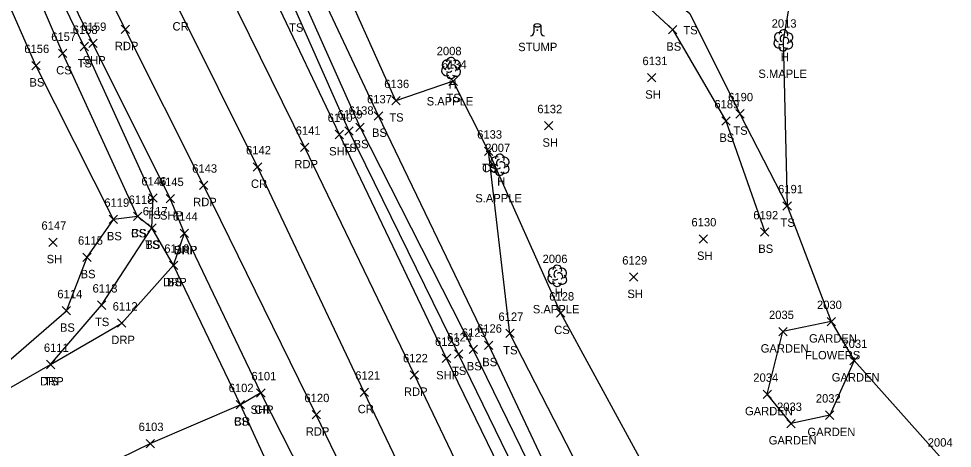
# Model space of a CAD drawing. Extents: x 1439173 to 1457902, y 641926 to 659889.
# Drawn here: x 1448995.2 to 1449218.3, y 643333 to 643435.5 of the extents above; entities that cross this region are included whole.
import ezdxf

# ---------------------------------------------------------------- set-up
doc = ezdxf.new("R2010")
doc.units = 0
for name, color, linetype in [('L_A', 7, 'Continuous'), ('L_C', 7, 'Continuous'), ('L_I', 7, 'Continuous'), ('L_TIC', 7, 'Continuous'), ('LAPB', 7, 'Continuous'), ('LELB', 7, 'Continuous'), ('LSOGP', 7, 'Continuous'), ('LTD', 7, 'Continuous'), ('LTS', 7, 'Continuous'), ('P_A', 7, 'Continuous'), ('P_I', 7, 'Continuous'), ('P_TIC', 7, 'Continuous'), ('PET', 7, 'Continuous'), ('PRC', 7, 'Continuous'), ('PSP', 7, 'Continuous'), ('R_A', 7, 'Continuous'), ('R_I', 7, 'Continuous'), ('R_TIC', 7, 'Continuous'), ('RDP', 7, 'Continuous')]:
    doc.layers.add(name, color=color, linetype=linetype)

msp = doc.modelspace()

# ---------------------------------------------------------------- linework, layer by layer
at = {"layer": 'L_TIC'}
for points in [[(1449150.53, 643431.82), (1449152.53, 643433.82)], [(1449152.53, 643431.82), (1449150.53, 643433.82)], [(1449004.76, 643426.17), (1449006.76, 643428.17)], [(1449006.76, 643426.17), (1449004.76, 643428.17)], [(1449009.91, 643427.83), (1449011.91, 643429.83)], [(1449011.91, 643427.83), (1449009.91, 643429.83)], [(1448998.38, 643423.27), (1449000.38, 643425.27)], [(1449000.38, 643423.27), (1448998.38, 643425.27)], [(1449098.06, 643419.55), (1449100.06, 643421.55)], [(1449100.06, 643419.55), (1449098.06, 643421.55)], [(1449145.46, 643420.38), (1449147.46, 643422.38)], [(1449147.46, 643420.38), (1449145.46, 643422.38)], [(1449084.39, 643414.9), (1449086.39, 643416.9)], [(1449086.39, 643414.9), (1449084.39, 643416.9)], [(1449080.22, 643411.26), (1449082.22, 643413.26)], [(1449082.22, 643411.26), (1449080.22, 643413.26)], [(1449166.59, 643411.76), (1449168.59, 643413.76)], [(1449168.59, 643411.76), (1449166.59, 643413.76)], [(1449075.83, 643408.55), (1449077.83, 643410.55)], [(1449077.83, 643408.55), (1449075.83, 643410.55)], [(1449120.91, 643408.91), (1449122.91, 643410.91)], [(1449122.91, 643408.91), (1449120.91, 643410.91)], [(1449163.22, 643410.07), (1449165.22, 643412.07)], [(1449165.22, 643410.07), (1449163.22, 643412.07)], [(1449073.19, 643407.65), (1449075.19, 643409.65)], [(1449075.19, 643407.65), (1449073.19, 643409.65)], [(1449106.53, 643402.84), (1449108.53, 643404.84)], [(1449108.53, 643402.84), (1449106.53, 643404.84)], [(1449106.53, 643402.84), (1449108.53, 643404.84)], [(1449108.53, 643402.84), (1449106.53, 643404.84)], [(1449026.37, 643391.66), (1449028.37, 643393.66)], [(1449028.37, 643391.66), (1449026.37, 643393.66)], [(1449177.86, 643389.8), (1449179.86, 643391.8)], [(1449179.86, 643389.8), (1449177.86, 643391.8)], [(1449016.88, 643386.58), (1449018.88, 643388.58)], [(1449018.88, 643386.58), (1449016.88, 643388.58)], [(1449016.88, 643386.58), (1449018.88, 643388.58)], [(1449018.88, 643386.58), (1449016.88, 643388.58)], [(1449022.67, 643387.28), (1449024.67, 643389.28)], [(1449024.67, 643387.28), (1449022.67, 643389.28)], [(1449022.67, 643387.28), (1449024.67, 643389.28)], [(1449024.67, 643387.28), (1449022.67, 643389.28)], [(1449026.07, 643384.54), (1449028.07, 643386.54)], [(1449028.07, 643384.54), (1449026.07, 643386.54)], [(1449026.07, 643384.54), (1449028.07, 643386.54)], [(1449028.07, 643384.54), (1449026.07, 643386.54)], [(1449172.51, 643383.58), (1449174.51, 643385.58)], [(1449174.51, 643383.58), (1449172.51, 643385.58)], [(1449157.82, 643381.9), (1449159.82, 643383.9)], [(1449159.82, 643381.9), (1449157.82, 643383.9)], [(1449002.43, 643381.11), (1449004.43, 643383.11)], [(1449004.43, 643381.11), (1449002.43, 643383.11)], [(1449010.59, 643377.53), (1449012.59, 643379.53)], [(1449012.59, 643377.53), (1449010.59, 643379.53)], [(1449031.25, 643375.62), (1449033.25, 643377.62)], [(1449033.25, 643375.62), (1449031.25, 643377.62)], [(1449141.19, 643372.8), (1449143.19, 643374.8)], [(1449143.19, 643372.8), (1449141.19, 643374.8)], [(1449014.06, 643366.11), (1449016.06, 643368.11)], [(1449016.06, 643366.11), (1449014.06, 643368.11)], [(1449005.66, 643364.76), (1449007.66, 643366.76)], [(1449007.66, 643364.76), (1449005.66, 643366.76)], [(1449123.75, 643364.21), (1449125.75, 643366.21)], [(1449125.75, 643364.21), (1449123.75, 643366.21)], [(1449188.41, 643362.18), (1449190.41, 643364.18)], [(1449190.41, 643362.18), (1449188.41, 643364.18)], [(1449188.41, 643362.18), (1449190.41, 643364.18)], [(1449190.41, 643362.18), (1449188.41, 643364.18)], [(1449111.62, 643359.36), (1449113.62, 643361.36)], [(1449113.62, 643359.36), (1449111.62, 643361.36)], [(1449176.86, 643359.79), (1449178.86, 643361.79)], [(1449178.86, 643359.79), (1449176.86, 643361.79)], [(1449176.86, 643359.79), (1449178.86, 643361.79)], [(1449178.86, 643359.79), (1449176.86, 643361.79)], [(1449099.36, 643354.44), (1449101.36, 643356.44)], [(1449101.36, 643354.44), (1449099.36, 643356.44)], [(1449102.87, 643355.55), (1449104.87, 643357.55)], [(1449104.87, 643355.55), (1449102.87, 643357.55)], [(1449106.56, 643356.54), (1449108.56, 643358.54)], [(1449108.56, 643356.54), (1449106.56, 643358.54)], [(1449193.84, 643352.89), (1449195.84, 643354.89)], [(1449195.84, 643352.89), (1449193.84, 643354.89)], [(1449001.87, 643351.95), (1449003.87, 643353.95)], [(1449003.87, 643351.95), (1449001.87, 643353.95)], [(1449173.11, 643344.83), (1449175.11, 643346.83)], [(1449175.11, 643344.83), (1449173.11, 643346.83)], [(1449047.24, 643342.36), (1449049.24, 643344.36)], [(1449049.24, 643342.36), (1449047.24, 643344.36)], [(1449188.04, 643339.86), (1449190.04, 643341.86)], [(1449190.04, 643339.86), (1449188.04, 643341.86)], [(1449178.78, 643337.86), (1449180.78, 643339.86)], [(1449180.78, 643337.86), (1449178.78, 643339.86)]]:
    msp.add_lwpolyline(points, dxfattribs=at)
at = {"layer": 'LAPB'}
for points in [[(1449189.41, 643363.18), (1449194.84, 643353.89), (1449189.04, 643340.86), (1449179.78, 643338.86), (1449174.11, 643345.83), (1449177.86, 643360.79)], [(1449189.41, 643363.18), (1449177.86, 643360.79)]]:
    msp.add_lwpolyline(points, dxfattribs=at)
at = {"layer": 'LELB'}
for points in [[(1449002.87, 643352.95), (1449015.06, 643367.11), (1449027.07, 643385.54), (1449027.37, 643392.66), (1449010.91, 643428.83), (1448990.64, 643470.1), (1448981.71, 643489.28), (1448973.52, 643506.02), (1448960.88, 643532.41), (1448957.69, 643539.66), (1448946.95, 643564.12), (1448940.79, 643577.93), (1448919.27, 643624.16)], [(1449057.52, 643323.2), (1449048.24, 643343.36), (1449032.25, 643376.62), (1449027.07, 643385.54), (1449023.67, 643388.28), (1449017.88, 643387.58), (1448999.38, 643424.27), (1448981.06, 643465.9), (1448978.91, 643484.15), (1448958.17, 643480.5)], [(1449023.67, 643388.28), (1449005.76, 643427.17), (1448987.76, 643468.8), (1448978.91, 643484.15)], [(1449171.86, 643204.27), (1449152.52, 643247.03), (1449132.22, 643288.76), (1449122.38, 643310.12), (1449100.36, 643355.44), (1449074.19, 643408.65), (1449061.44, 643437.34), (1449058.46, 643446.18), (1449059.5, 643448.74), (1449063.87, 643451.99), (1449068.54, 643452.64), (1449093.96, 643455.36), (1449106.86, 643455.84), (1449118.71, 643456.31), (1449141.25, 643448.31), (1449155.64, 643436.72), (1449167.59, 643412.76), (1449178.86, 643390.8)], [(1449185.52, 643209.06), (1449166.12, 643252.93), (1449146.62, 643293.4), (1449135.25, 643316.37), (1449112.62, 643360.36), (1449107.53, 643403.84), (1449099.06, 643420.55), (1449085.39, 643415.9), (1449070.11, 643449.83), (1449068.54, 643452.64)], [(1449118.97, 643452.28), (1449140.04, 643443.48), (1449151.53, 643432.82), (1449164.22, 643411.07), (1449173.51, 643384.58)], [(1449127.84, 643314.62), (1449107.56, 643357.54), (1449081.22, 643412.26), (1449064.59, 643447.64), (1449062.09, 643448.65), (1449060.63, 643447.6), (1449062.19, 643442.41)], [(1449125.22, 643312.87), (1449103.87, 643356.55), (1449076.83, 643409.55), (1449062.19, 643442.41)], [(1449197.24, 643213.11), (1449176.08, 643257.09), (1449156.69, 643299.92), (1449147.93, 643322.72), (1449124.75, 643365.21), (1449107.53, 643403.84)], [(1448958.67, 643334.28), (1448987.94, 643349.59), (1449006.66, 643365.76), (1449011.59, 643378.53), (1449017.88, 643387.58)]]:
    msp.add_lwpolyline(points, dxfattribs=at)
at = {"layer": 'LSOGP'}
msp.add_lwpolyline([(1449183.75, 643464.06), (1449177.92, 643430.32), (1449178.86, 643390.8), (1449189.41, 643363.18), (1449194.83, 643353.9), (1449215.87, 643330.35)], dxfattribs=at)
at = {"layer": 'LTD'}
for p, q in [((1449177.92, 643430.32), (1449177.92, 643430.32)), ((1449177.92, 643430.32), (1449177.92, 643430.32)), ((1449098.54, 643423.75), (1449098.54, 643423.75)), ((1449098.54, 643423.75), (1449098.54, 643423.75)), ((1449110.15, 643400.64), (1449110.15, 643400.64)), ((1449110.15, 643400.64), (1449110.15, 643400.64)), ((1449123.9, 643374.15), (1449123.9, 643374.15)), ((1449123.9, 643374.15), (1449123.9, 643374.15))]:
    msp.add_line(p, q, dxfattribs=at)
for centre in [(1449177.97, 643431.76), (1449098.58, 643425.19), (1449110.2, 643402.07), (1449123.94, 643375.58)]:
    msp.add_arc(centre, 1.05, 335.5272, 180.9563, dxfattribs=at)
for centre, major_axis, ratio, start_param, end_param in [((1449177.13, 643430.99), (1.21, -0.51), 0.895232, 1.570796, 4.712389), ((1449178.96, 643430.91), (-1.14, -0.48), 0.949671, 1.570796, 4.712389), ((1449176.84, 643429.61), (0.58, -1.04), 0.959034, 3.141593, 6.283185), ((1449177.71, 643430.78), (-0.208, -0.792), 0.645439, 3.141593, 6.283185), ((1449178.42, 643430.16), (-0.5, 0.667), 0.989748, 3.141593, 6.283185), ((1449178.92, 643429.49), (-1.09, 0.79), 0.841452, 1.570796, 4.712389), ((1449177.92, 643428.82), (0.26, 1.06), 0.942809, 1.570796, 4.712389), ((1449177.46, 643429.57), (-0.625, -0.083), 0.423636, 0, 3.141593), ((1449097.74, 643424.42), (1.21, -0.51), 0.895232, 1.570796, 4.712389), ((1449099.58, 643424.34), (-1.14, -0.48), 0.949671, 1.570796, 4.712389), ((1449097.45, 643423.04), (0.58, -1.04), 0.959034, 3.141593, 6.283185), ((1449098.33, 643424.21), (-0.208, -0.792), 0.645439, 3.141593, 6.283185), ((1449099.04, 643423.59), (-0.5, 0.667), 0.989748, 3.141593, 6.283185), ((1449099.54, 643422.92), (-1.09, 0.79), 0.841452, 1.570796, 4.712389), ((1449098.54, 643422.25), (0.26, 1.06), 0.942809, 1.570796, 4.712389), ((1449098.08, 643423), (-0.625, -0.083), 0.423636, 0, 3.141593), ((1449109.36, 643401.31), (1.21, -0.51), 0.895232, 1.570796, 4.712389), ((1449109.94, 643401.1), (-0.208, -0.792), 0.645439, 3.141593, 6.283185), ((1449110.65, 643400.47), (-0.5, 0.667), 0.989748, 3.141593, 6.283185), ((1449111.19, 643401.22), (-1.14, -0.48), 0.949671, 1.570796, 4.712389), ((1449109.07, 643399.93), (0.58, -1.04), 0.959034, 3.141593, 6.283185), ((1449110.15, 643399.14), (0.26, 1.06), 0.942809, 1.570796, 4.712389), ((1449109.69, 643399.89), (-0.625, -0.083), 0.423636, 0, 3.141593), ((1449111.15, 643399.81), (-1.09, 0.79), 0.841452, 1.570796, 4.712389), ((1449122.81, 643373.44), (0.58, -1.04), 0.959034, 3.141593, 6.283185), ((1449123.11, 643374.82), (1.21, -0.51), 0.895232, 1.570796, 4.712389), ((1449123.69, 643374.61), (-0.208, -0.792), 0.645439, 3.141593, 6.283185), ((1449124.4, 643373.98), (-0.5, 0.667), 0.989748, 3.141593, 6.283185), ((1449124.94, 643374.73), (-1.14, -0.48), 0.949671, 1.570796, 4.712389), ((1449123.9, 643372.65), (0.26, 1.06), 0.942809, 1.570796, 4.712389), ((1449123.44, 643373.4), (-0.625, -0.083), 0.423636, 0, 3.141593), ((1449124.9, 643373.32), (-1.09, 0.79), 0.841452, 1.570796, 4.712389)]:
    msp.add_ellipse(centre, major_axis=major_axis, ratio=ratio, start_param=start_param, end_param=end_param, dxfattribs=at)
at = {"layer": 'LTS'}
for p, q in [((1449118.34, 643433.86), (1449118.34, 643432.19)), ((1449119.17, 643432.71), (1449119.17, 643432.71)), ((1449119.17, 643432.71), (1449119.17, 643432.71)), ((1449119.17, 643432.69), (1449119.17, 643432.69)), ((1449120, 643433.69), (1449120, 643433.86)), ((1449120, 643433.86), (1449120, 643432.19))]:
    msp.add_line(p, q, dxfattribs=at)
msp.add_circle((1449119.17, 643432.71), 0.0833, dxfattribs=at)
for centre, start, end in [((1449117.5, 643432.19), 270, 360), ((1449120.84, 643432.19), 180, 270)]:
    msp.add_arc(centre, 0.833, start, end, dxfattribs=at)
msp.add_ellipse((1449119.17, 643433.86), major_axis=(-0.833, 0), ratio=0.5, dxfattribs=at)
at = {"layer": 'P_TIC'}
for points in [[(1449019.72, 643431.95), (1449021.72, 643433.95)], [(1449021.72, 643431.95), (1449019.72, 643433.95)], [(1449011.98, 643428.55), (1449013.98, 643430.55)], [(1449013.98, 643428.55), (1449011.98, 643430.55)], [(1449070.88, 643406.83), (1449072.88, 643408.83)], [(1449072.88, 643406.83), (1449070.88, 643408.83)], [(1449062.61, 643403.76), (1449064.61, 643405.76)], [(1449064.61, 643403.76), (1449062.61, 643405.76)], [(1449051.31, 643399.08), (1449053.31, 643401.08)], [(1449053.31, 643399.08), (1449051.31, 643401.08)], [(1449038.44, 643394.72), (1449040.44, 643396.72)], [(1449040.44, 643394.72), (1449038.44, 643396.72)], [(1449030.47, 643391.52), (1449032.47, 643393.52)], [(1449032.47, 643391.52), (1449030.47, 643393.52)], [(1449033.83, 643383.26), (1449035.83, 643385.26)], [(1449035.83, 643383.26), (1449033.83, 643385.26)], [(1449096.46, 643353.4), (1449098.46, 643355.4)], [(1449098.46, 643353.4), (1449096.46, 643355.4)], [(1449088.8, 643349.47), (1449090.8, 643351.47)], [(1449090.8, 643349.47), (1449088.8, 643351.47)], [(1449052.1, 643345.18), (1449054.1, 643347.18)], [(1449054.1, 643345.18), (1449052.1, 643347.18)], [(1449052.1, 643345.18), (1449054.1, 643347.18)], [(1449054.1, 643345.18), (1449052.1, 643347.18)], [(1449076.82, 643345.33), (1449078.82, 643347.33)], [(1449078.82, 643345.33), (1449076.82, 643347.33)], [(1449047.24, 643342.36), (1449049.24, 643344.36)], [(1449049.24, 643342.36), (1449047.24, 643344.36)], [(1449065.34, 643339.97), (1449067.34, 643341.97)], [(1449067.34, 643339.97), (1449065.34, 643341.97)], [(1449025.71, 643333.07), (1449027.71, 643335.07)], [(1449027.71, 643333.07), (1449025.71, 643335.07)]]:
    msp.add_lwpolyline(points, dxfattribs=at)
at = {"layer": 'PET'}
for points in [[(1449162.58, 643198.27), (1449141.48, 643242.39), (1449121.69, 643284.02), (1449089.8, 643350.47), (1449063.61, 643404.76), (1449045.09, 643442.41), (1449024.86, 643484.45), (1449010.1, 643514.11), (1448990.81, 643553.04), (1448970.84, 643592.72), (1448947.22, 643637.96), (1448929.6, 643671.83), (1448913.03, 643703.21), (1448880.27, 643765.4), (1448860.14, 643803.65), (1448849.29, 643824.32), (1448831.93, 643857), (1448813.55, 643891.18), (1448792.86, 643930.51), (1448774.91, 643964.18), (1448756.71, 643999.72), (1448741.68, 644029.9), (1448721.66, 644072.11)], [(1449139.97, 643188.13), (1449117.6, 643232.77), (1449099.11, 643273.2), (1449066.34, 643340.97), (1449039.44, 643395.72), (1449020.72, 643432.95), (1449000.27, 643474.21), (1448984.45, 643505.7), (1448966.63, 643542.12), (1448946.78, 643580.8), (1448923.53, 643626.67), (1448906.33, 643660.76), (1448890.57, 643691.55), (1448882.77, 643706.14), (1448861.66, 643747.38), (1448842.89, 643782.5), (1448829.18, 643808.28), (1448815.05, 643835.06), (1448764.92, 643929.88), (1448739.21, 643978.47), (1448719.14, 644017.8), (1448697.57, 644061.64)]]:
    msp.add_lwpolyline(points, dxfattribs=at)
at = {"layer": 'PRC'}
for points in [[(1449151.13, 643193.26), (1449129.92, 643237.18), (1449110.21, 643278.66), (1449077.82, 643346.33), (1449052.31, 643400.08), (1449033.57, 643437.64), (1449013.31, 643480.22), (1448998.17, 643509.98), (1448979.42, 643547.94), (1448960, 643587.03), (1448936.54, 643632.54), (1448918.64, 643666.68), (1448902.12, 643697.96), (1448893.71, 643713.68), (1448873.04, 643753.33), (1448854.51, 643788.55), (1448840.55, 643814.74), (1448825.9, 643842.48), (1448798.39, 643894.2), (1448777.05, 643935.06), (1448750.78, 643985.2), (1448731.14, 644023.28), (1448710.46, 644067.89)], [(1449053.1, 643346.18), (1449048.24, 643343.36), (1449026.71, 643334.07), (1449004.57, 643323.28), (1448976.4, 643308.88)]]:
    msp.add_lwpolyline(points, dxfattribs=at)
at = {"layer": 'PSP'}
for points in [[(1449169.82, 643203.27), (1449149.93, 643245.98), (1449130.54, 643285.72), (1449118.39, 643311.34), (1449097.46, 643354.4), (1449071.88, 643407.83), (1449056.01, 643441.14), (1449042.63, 643467.59), (1449032.61, 643488.35), (1449017.97, 643518.51), (1449011.01, 643533.15), (1448991.34, 643572.89), (1448977.12, 643597.86), (1448952.22, 643640.32)], [(1449131.44, 643184.41), (1449109.56, 643229.09), (1449090.46, 643269.75), (1449065.76, 643321.33), (1449053.1, 643346.18), (1449034.83, 643384.26), (1449031.47, 643392.52), (1449012.98, 643429.55), (1448992.54, 643471.26), (1448985.02, 643487.75), (1448974.42, 643508.35), (1448960.29, 643539.72), (1448943.46, 643579.59), (1448921.84, 643625.91)]]:
    msp.add_lwpolyline(points, dxfattribs=at)
at = {"layer": 'R_TIC'}
for points in [[(1449033.83, 643383.26), (1449035.83, 643385.26)], [(1449035.83, 643383.26), (1449033.83, 643385.26)], [(1449031.25, 643375.62), (1449033.25, 643377.62)], [(1449033.25, 643375.62), (1449031.25, 643377.62)], [(1449018.88, 643361.82), (1449020.88, 643363.82)], [(1449020.88, 643361.82), (1449018.88, 643363.82)], [(1449001.87, 643351.95), (1449003.87, 643353.95)], [(1449003.87, 643351.95), (1449001.87, 643353.95)]]:
    msp.add_lwpolyline(points, dxfattribs=at)
at = {"layer": 'RDP'}
msp.add_lwpolyline([(1448963.13, 643329.54), (1448990.18, 643345.74), (1449002.87, 643352.95), (1449019.88, 643362.82), (1449032.25, 643376.62), (1449034.83, 643384.26)], dxfattribs=at)

# ---------------------------------------------------------------- texts
at = {"layer": 'L_A'}
for s, p in [('TS', (1449059.85, 643432.34)), ('TS', (1449154.05, 643431.72)), ('STUMP', (1449114.59, 643427.72)), ('BS', (1449149.97, 643427.82)), ('TS', (1449009.32, 643423.83)), ('H', (1449177.35, 643425.32)), ('CS', (1449004.2, 643422.17)), ('BS', (1448997.82, 643419.27)), ('H', (1449097.97, 643418.75)), ('TS', (1449097.47, 643415.55)), ('SH', (1449144.95, 643416.38)), ('TS', (1449083.8, 643410.9)), ('BS', (1449079.66, 643407.26)), ('BS', (1449162.66, 643406.07)), ('TS', (1449166, 643407.76)), ('TS', (1449072.6, 643403.65)), ('BS', (1449075.27, 643404.55)), ('SH', (1449120.4, 643404.91)), ('TS', (1449105.94, 643398.84)), ('CS', (1449105.97, 643398.84)), ('H', (1449109.58, 643395.64)), ('TS', (1449025.78, 643387.66)), ('TS', (1449177.27, 643385.8)), ('BS', (1449016.32, 643382.58)), ('BS', (1449016.32, 643382.58)), ('CS', (1449022.11, 643383.28)), ('BS', (1449022.11, 643383.28)), ('TS', (1449025.48, 643380.54)), ('BS', (1449025.51, 643380.54)), ('BS', (1449171.95, 643379.58)), ('SH', (1449001.92, 643377.11)), ('SH', (1449157.31, 643377.9)), ('BS', (1449010.04, 643373.53)), ('BS', (1449030.69, 643371.62)), ('H', (1449123.33, 643369.15)), ('SH', (1449140.68, 643368.8)), ('TS', (1449013.47, 643362.11)), ('BS', (1449005.1, 643360.76)), ('CS', (1449123.19, 643360.21)), ('GARDEN', (1449184.08, 643358.18)), ('GARDEN', (1449184.08, 643358.18)), ('TS', (1449111.02, 643355.36)), ('GARDEN', (1449172.53, 643355.79)), ('GARDEN', (1449172.53, 643355.79)), ('BS', (1449106, 643352.54)), ('TS', (1449098.77, 643350.44)), ('BS', (1449102.31, 643351.55)), ('TS', (1449001.28, 643347.95)), ('GARDEN', (1449189.51, 643348.89)), ('GARDEN', (1449168.78, 643340.83)), ('BS', (1449046.68, 643338.36)), ('GARDEN', (1449183.71, 643335.86)), ('GARDEN', (1449174.45, 643333.86))]:
    msp.add_text(s, height=2, dxfattribs=at).set_placement(p)
at = {"layer": 'L_C'}
for s, p in [('S.MAPLE', (1449171.98, 643421.32)), ('S.APPLE', (1449092.72, 643414.75)), ('S.APPLE', (1449104.34, 643391.64)), ('S.APPLE', (1449118.09, 643365.15)), ('FLOWERS', (1449183.11, 643354.18)), ('FLOWERS', (1449183.11, 643354.18))]:
    msp.add_text(s, height=2, dxfattribs=at).set_placement(p)
at = {"layer": 'L_I'}
for s, p in [('2013', (1449175.15, 643433.32)), ('6158', (1449008.17, 643431.83)), ('6157', (1449003.02, 643430.17)), ('6156', (1448996.59, 643427.27)), ('2008', (1449095.12, 643426.75)), ('6134', (1449096.32, 643423.55)), ('6131', (1449144.29, 643424.38)), ('6136', (1449082.59, 643418.9)), ('6137', (1449078.48, 643415.26)), ('6190', (1449164.76, 643415.76)), ('6138', (1449074.09, 643412.55)), ('6132', (1449119.17, 643412.91)), ('6189', (1449161.47, 643414.07)), ('6139', (1449071.44, 643411.65)), ('6133', (1449104.79, 643406.84)), ('6133', (1449104.79, 643406.84)), ('2007', (1449106.73, 643403.64)), ('6146', (1449024.58, 643395.66)), ('6191', (1449176.69, 643393.8)), ('6119', (1449015.7, 643390.58)), ('6119', (1449015.7, 643390.58)), ('6118', (1449021.5, 643391.28)), ('6118', (1449021.5, 643391.28)), ('6117', (1449024.9, 643388.54)), ('6117', (1449024.9, 643388.54)), ('6130', (1449155.99, 643385.9)), ('6192', (1449170.77, 643387.58)), ('6147', (1449000.69, 643385.11)), ('6115', (1449009.42, 643381.53)), ('6116', (1449030.03, 643379.62)), ('2006', (1449120.42, 643377.15)), ('6129', (1449139.45, 643376.8)), ('6113', (1449012.89, 643370.11)), ('6114', (1449004.49, 643368.76)), ('6128', (1449122.01, 643368.21)), ('2030', (1449185.98, 643366.18)), ('2030', (1449185.98, 643366.18)), ('6127', (1449109.88, 643363.36)), ('2035', (1449174.52, 643363.79)), ('2035', (1449174.52, 643363.79)), ('6125', (1449101.13, 643359.55)), ('6126', (1449104.76, 643360.54)), ('6124', (1449097.62, 643358.44)), ('2031', (1449192.07, 643356.89)), ('6111', (1449001.27, 643355.95)), ('2034', (1449170.77, 643348.83)), ('6102', (1449045.42, 643346.36)), ('2032', (1449185.71, 643343.86)), ('2033', (1449176.44, 643341.86)), ('2004', (1449212.45, 643333.35))]:
    msp.add_text(s, height=2, dxfattribs=at).set_placement(p)
at = {"layer": 'P_A'}
for s, p in [('CR', (1449032, 643432.64)), ('RDP', (1449018.21, 643427.95)), ('SHP', (1449010.52, 643424.55)), ('SHP', (1449069.42, 643402.83)), ('RDP', (1449061.1, 643399.76)), ('CR', (1449050.74, 643395.08)), ('RDP', (1449036.93, 643390.72)), ('SHP', (1449029.01, 643387.52)), ('SHP', (1449032.36, 643379.26)), ('SHP', (1449094.99, 643349.4)), ('RDP', (1449087.29, 643345.47)), ('SHP', (1449050.64, 643341.18)), ('CR', (1449051.54, 643341.18)), ('CR', (1449076.25, 643341.33)), ('CR', (1449046.68, 643338.36)), ('RDP', (1449063.83, 643335.97))]:
    msp.add_text(s, height=2, dxfattribs=at).set_placement(p)
at = {"layer": 'P_I'}
for s, p in [('6159', (1449010.24, 643432.55)), ('6140', (1449069.06, 643410.83)), ('6141', (1449061.43, 643407.76)), ('6142', (1449049.57, 643403.08)), ('6143', (1449036.7, 643398.72)), ('6145', (1449028.73, 643395.52)), ('6144', (1449032.09, 643387.26)), ('6123', (1449094.72, 643357.4)), ('6122', (1449087.06, 643353.47)), ('6101', (1449050.85, 643349.18)), ('6101', (1449050.85, 643349.18)), ('6121', (1449075.65, 643349.33)), ('6102', (1449045.42, 643346.36)), ('6120', (1449063.52, 643343.97)), ('6103', (1449023.9, 643337.07))]:
    msp.add_text(s, height=2, dxfattribs=at).set_placement(p)
at = {"layer": 'R_A'}
for p in [(1449032.32, 643379.26), (1449029.74, 643371.62), (1449017.37, 643357.82), (1449000.36, 643347.95)]:
    msp.add_text('DRP', height=2, dxfattribs=at).set_placement(p)
at = {"layer": 'R_I'}
for s, p in [('6144', (1449032.09, 643387.26)), ('6116', (1449030.03, 643379.62)), ('6112', (1449017.71, 643365.82)), ('6111', (1449001.27, 643355.95))]:
    msp.add_text(s, height=2, dxfattribs=at).set_placement(p)

doc.saveas('drawing.dxf')
